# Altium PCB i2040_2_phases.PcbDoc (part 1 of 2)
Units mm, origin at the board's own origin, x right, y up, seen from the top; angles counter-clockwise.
Board outline 90 x 90 mm, 2 copper layers (Top Layer, Bottom Layer), stack 1.575 mm thick; 116 components, 66 nets, 276 pads, 142 vias.
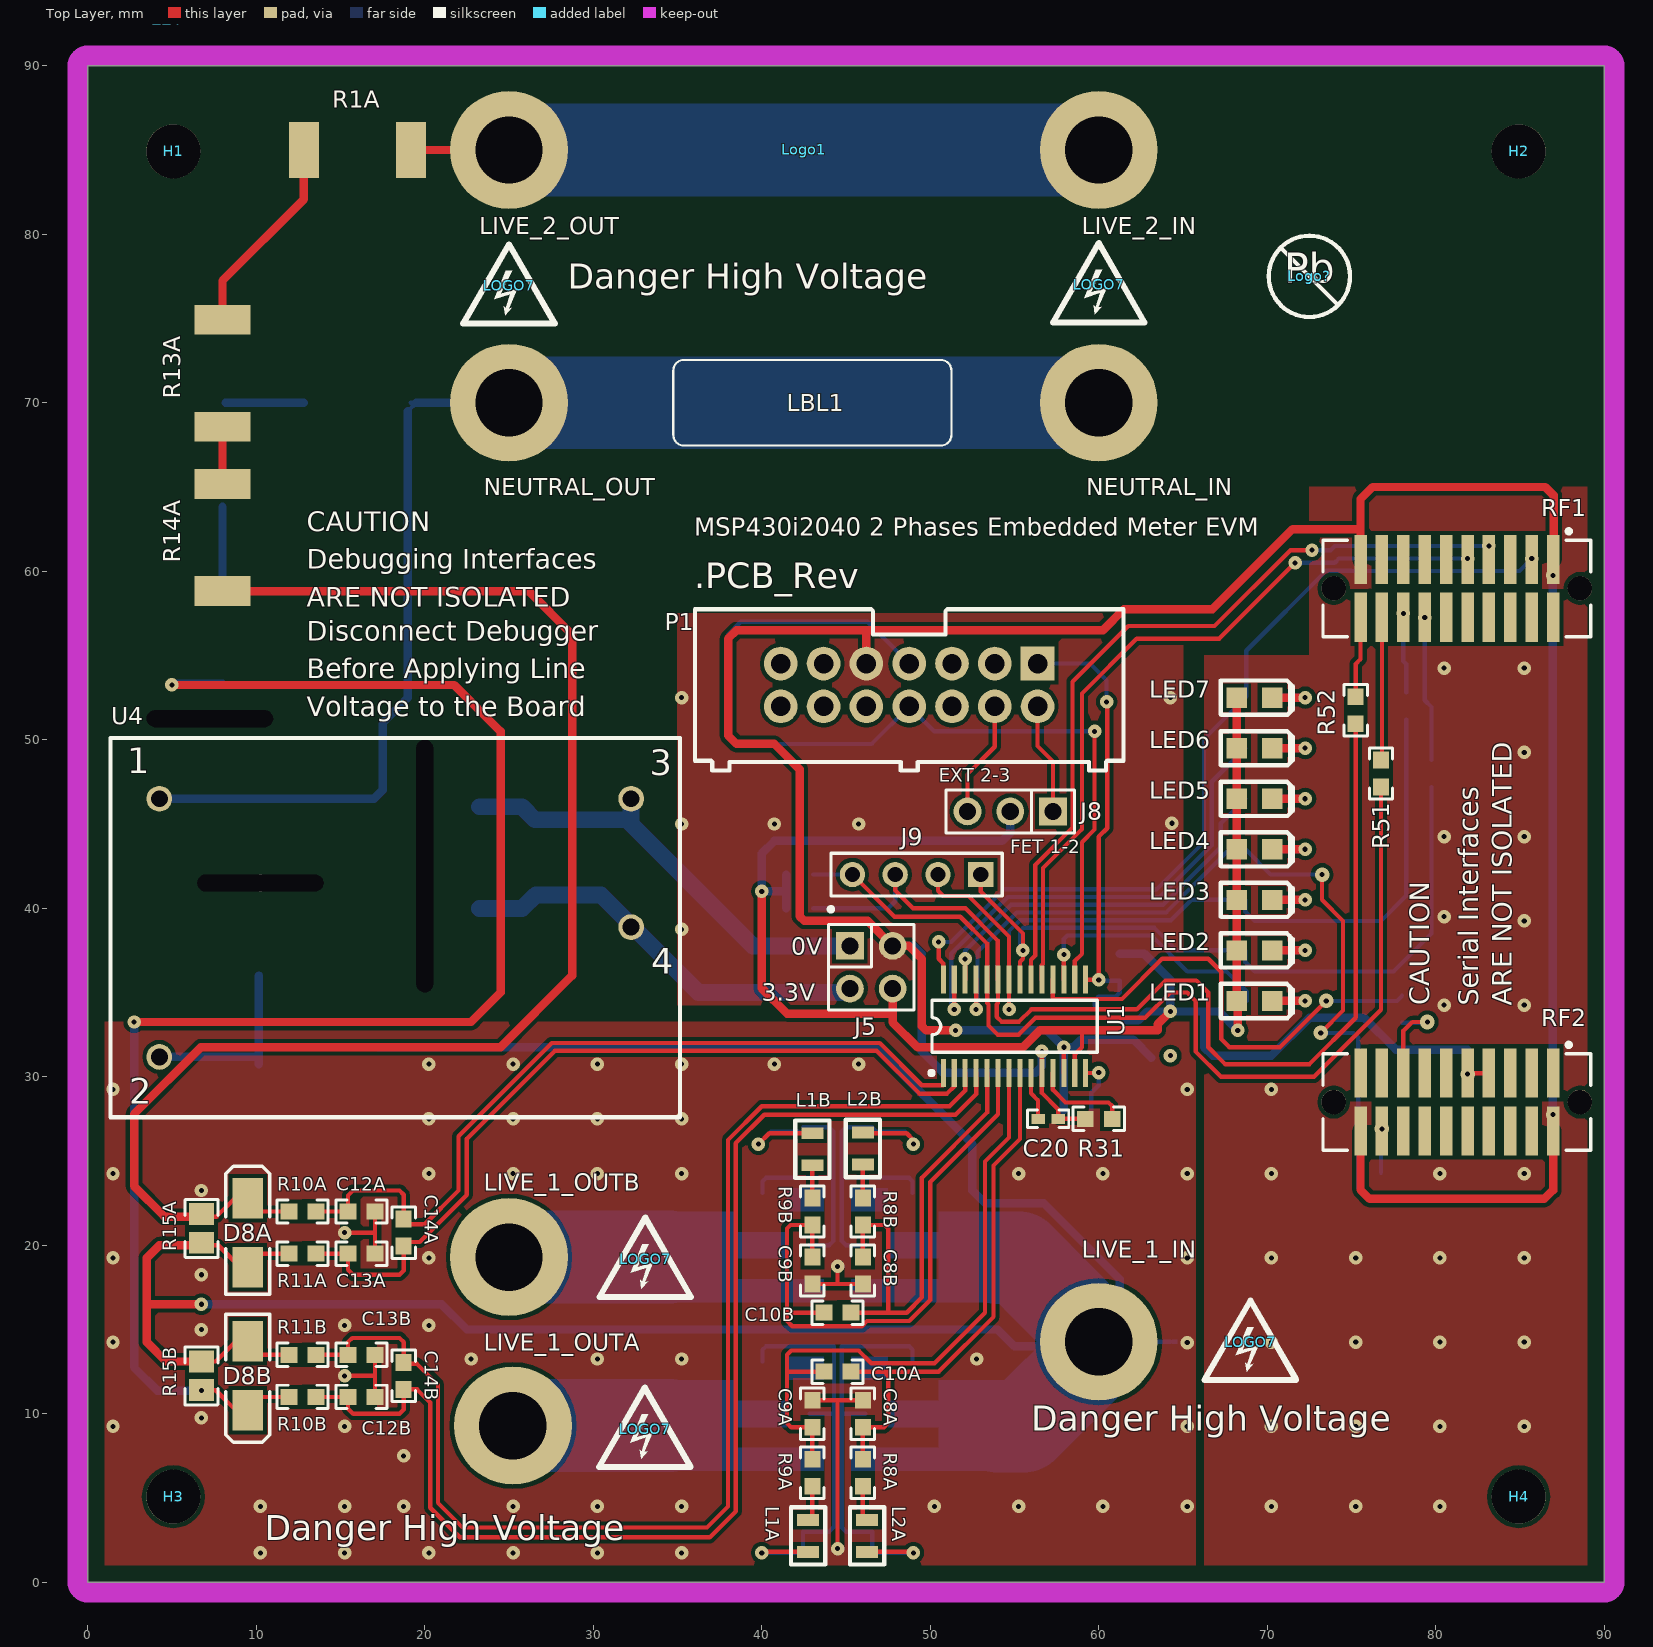
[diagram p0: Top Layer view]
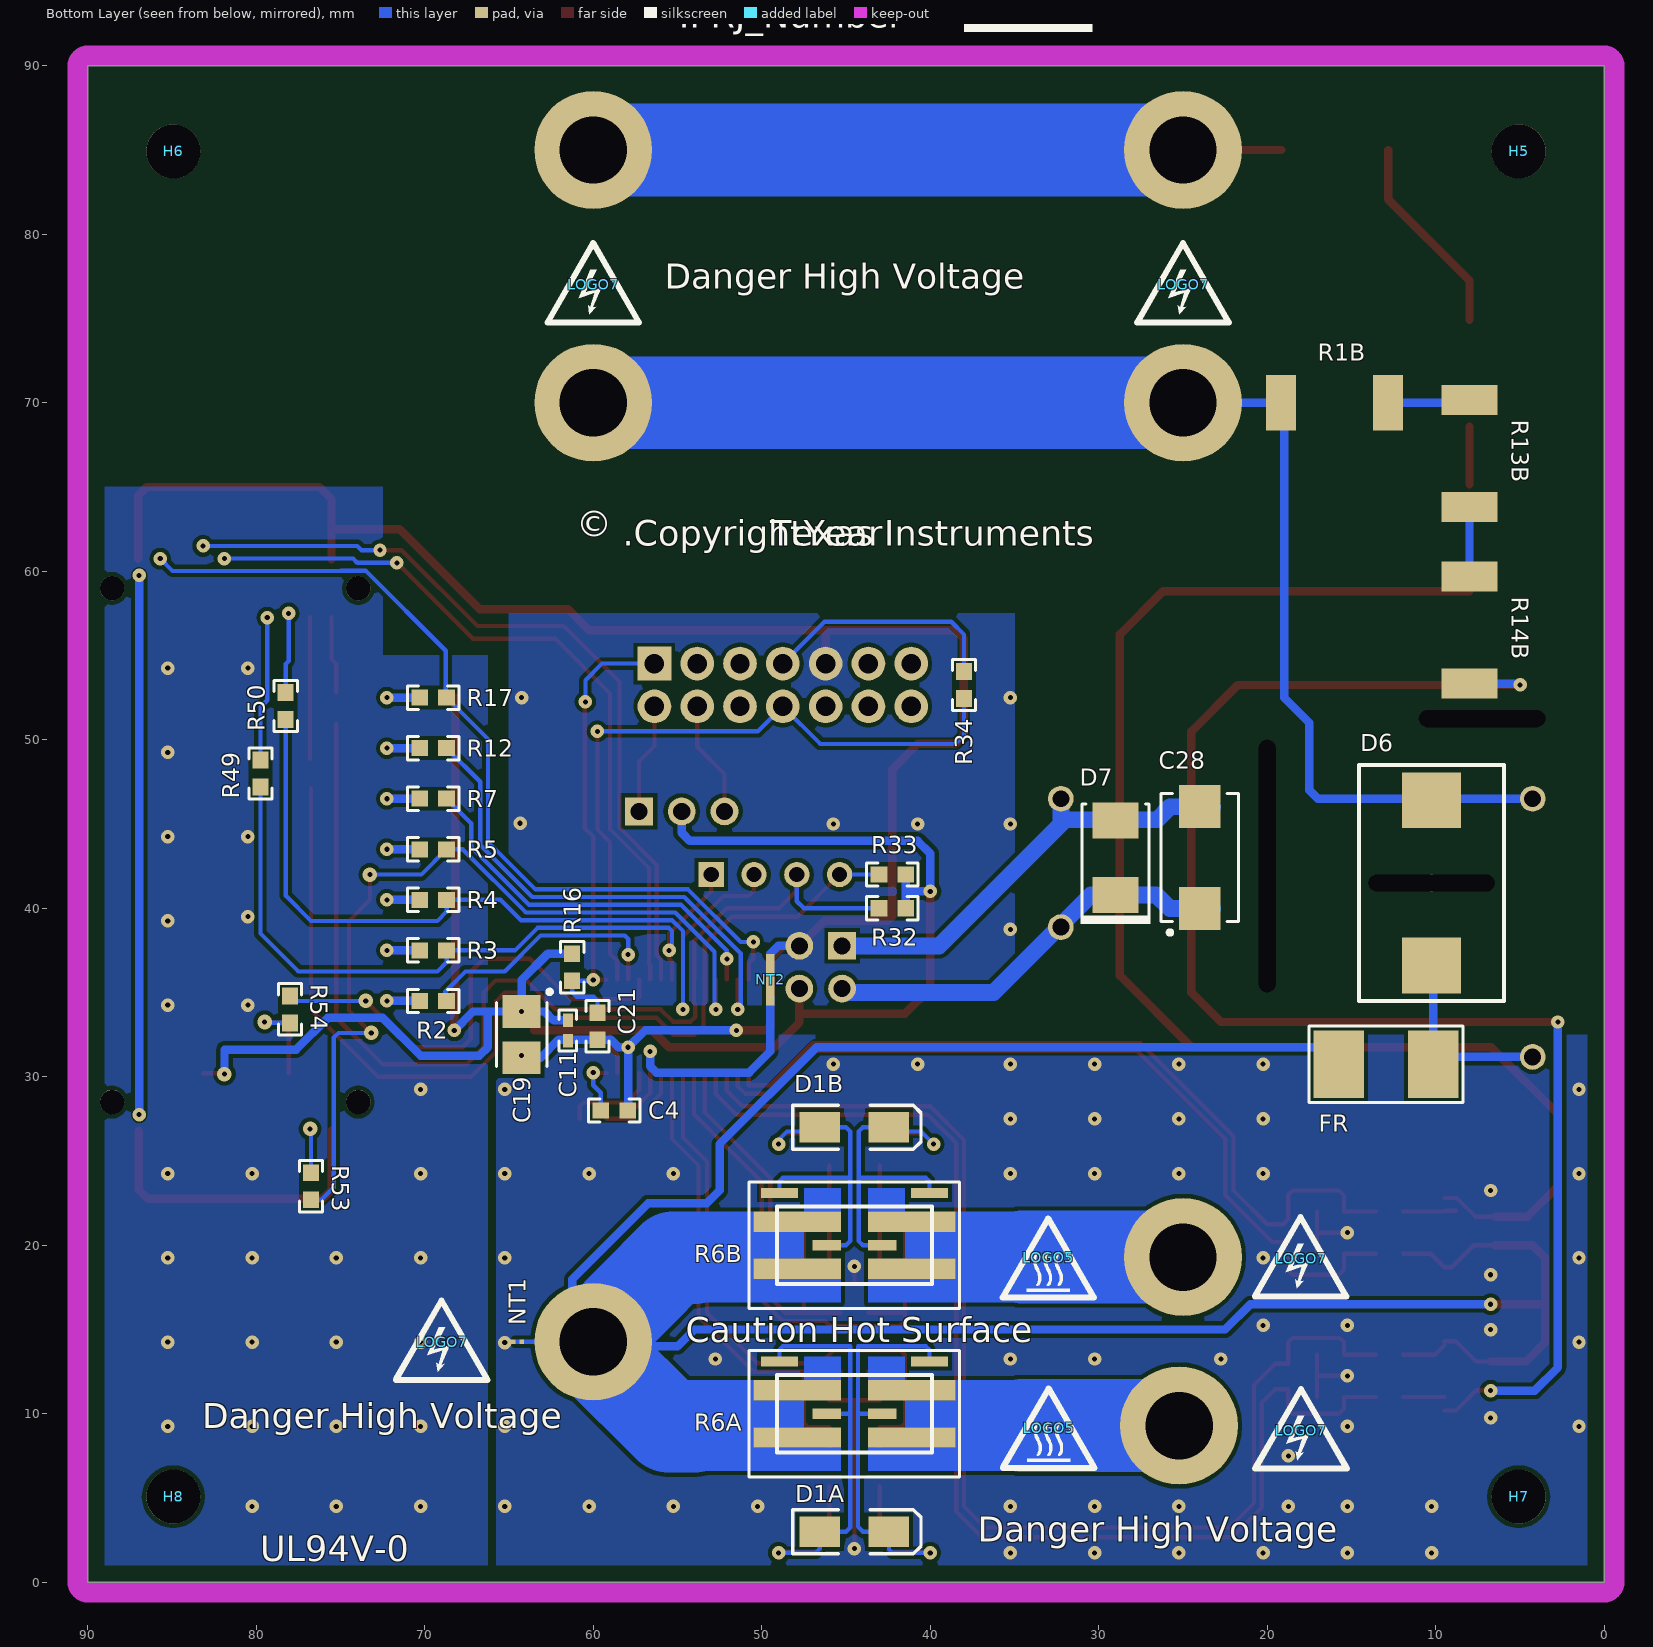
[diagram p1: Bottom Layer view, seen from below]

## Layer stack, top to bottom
Top Layer: signal copper 0.0356
Dielectric: core 1.5037, FR-4, Dk 4.8
Bottom Layer: signal copper 0.0356

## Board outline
0,0 90,0 90,90 0,90

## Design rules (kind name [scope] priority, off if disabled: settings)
AcuteAngle [All] p1: minimum=4.50000000000000E+0001 checktracksonly=FALSE
AssemblyTestPointUsage [All] p1: valid=2
Clearance Clearance_HV [InNet('LIVE2') vs OnLayer('Bottom Layer')] p1: gap=8
Clearance Clearance_BoardEdge_MountingHoles [OnCopper and InComponentClass('Mounting Holes') vs IsKeepOut] p2: gap=1.016
Clearance Clearance_BoardEdge_Poly [OnCopper and InPoly vs IsKeepOut] p3: gap=0.635
Clearance Clearance_BoardEdge [All vs IsKeepOut] p4: gap=1
Clearance Clearance_Poly [InPolygon] p5: gap=0.25
Clearance [All] p6: gap=0.203
ComponentClearance ComponentClearance_Shunt [InComponentClass('Header') vs InComponentClass('Shunt')] p1: gap=0 collisioncheckmode=3 verticalgap=0 showdistances=FALSE
ComponentClearance ComponentClearance_Logo [InComponentClass('Logo')] p2: gap=1.27 collisioncheckmode=3 verticalgap=0.254 showdistances=FALSE
ComponentClearance ComponentClearance_ScrewToNut [(HasFootprint('NY PMS 440 0025 PH')) vs (HasFootprint('Keystone_1902C'))] p3: gap=0.127 collisioncheckmode=3 verticalgap=0.254 showdistances=FALSE
ComponentClearance ComponentClearance_MountingHoles [InComponentClass('Mounting Holes')] p4: gap=5 collisioncheckmode=3 verticalgap=0 showdistances=FALSE
ComponentClearance ComponentClearance_SmallPassives [HasFootprint('0201*') or HasFootprint('0402*') or HasFootprint('0508') or HasFootprint('0603*') or HasFootprint('0612') or HasFootprint('0805*') or HasFootprint('0815*') or HasFootprint('0830*') or HasFootprint('1206*') or HasFootprint('1210*') or HasFootprint('1808*') or HasFootprint('1812*') or HasFootprint('1825*') or HasFootprint('2010*') or HasFootprint('2220*') or HasFootprint('2225*') or HasFootprint('2512*') or HasFootprint('2728*') or HasFootprint('3518*') vs HasFootprint('0201*') or HasFootprint('0402*') or HasFootprint('0508') or HasFootprint('0603*') or HasFootprint('0612') or HasFootprint('0805*') or HasFootprint('0815*') or HasFootprint('0830*') or HasFootprint('1206*') or HasFootprint('1210*') or HasFootprint('1808*') or HasFootprint('1812*') or HasFootprint('1825*') or HasFootprint('2010*') or HasFootprint('2220*') or HasFootprint('2225*') or HasFootprint('2512*') or HasFootprint('2728*') or HasFootprint('3518*')] p5: gap=0.5 collisioncheckmode=3 verticalgap=0.254 showdistances=FALSE
ComponentClearance ComponentClearance_THtoSMT [IsThruComponent vs IsSMTComponent] p6: gap=0.5 collisioncheckmode=3 verticalgap=0.762 showdistances=FALSE
ComponentClearance ComponentClearance_THtoTH [IsThruComponent vs IsThruComponent] p7: gap=1 collisioncheckmode=3 verticalgap=0.762 showdistances=FALSE
ComponentClearance [All] p8: gap=0.5 collisioncheckmode=3 verticalgap=0.254 showdistances=FALSE
DiffPairsRouting [All] p1: maxlimit=2.54 minlimit=0.254 mostfreqgap=0.254 maxuncoupledlength=25.4
FabricationTestPointUsage TestPointUsage [All] p1: valid=2 allowmultiple=FALSE
FabricationTestpoint Testpoint [All] p1: side=3 testpointundercomponent=TRUE minsize=1.016 maxsize=2.54 preferedsize=1.524 minholesize=0 maxholesize=1.016 preferedholesize=0.813 testpointgrid=0.025 allowsidetop=TRUE allowsidebottom=TRUE usegrid=TRUE gridtolerance=0
FanoutControl Fanout_LCC [IsLCC] p1: bgadir=Out bgaviamode=Centered fanoutstyle=Auto fanoutdirection=Alternating viagrid=0.025 // Fanout_LCC (Default Rule)
FanoutControl Fanout_BGA [IsBGA] p2: bgadir=Out bgaviamode=Centered fanoutstyle=Auto fanoutdirection=Alternating viagrid=0.025 // Fanout_BGA (Default Rule)
FanoutControl Fanout_Default [All] p4: bgadir=Out bgaviamode=Centered fanoutstyle=Auto fanoutdirection=Alternating viagrid=0.025 // Fanout_Default (Default Rule)
FanoutControl Fanout_Small [(CompPinCount < 5)] p5: bgadir=Out bgaviamode=Centered fanoutstyle=Auto fanoutdirection=OutThenIn viagrid=0.025 // Fanout_Small (Default Rule)
HoleSize [All] p1: absolutevalues=TRUE maxlimit=6.375 minlimit=0.203 maxpercent=80.000 minpercent=20.000
MinimumAnnularRing MinimumAnnularRing_ThermalPadVias [IsVia and InAnyComponent] p1: minimumring=0.15
MinimumAnnularRing [All] p2: minimumring=0.229
MinimumSolderMaskSliver MinimumSolderMaskSliver_Logo [InComponentClass('Logo') vs InComponentClass('Logo')] p1: minsoldermaskwidth=0.018
MinimumSolderMaskSliver [All] p2: minsoldermaskwidth=0.1
PlaneConnect [All] p1: planeconnectstyle=Relief reliefexpansion=0.254 reliefentries=4 reliefconductorwidth=0.254 reliefairgap=0.254
PolygonConnect [All] p1: connectstyle=Direct reliefconductorwidth=0.254 reliefentries=4 polygonreliefangle="90 Angle" airgapwidth=0.254
RoutingVias ThermalPadVias [IsVia and InAnyComponent] p1: holewidth=0.2 width=0.5 viastyle="Through Hole" minholewidth=0.2 minwidth=0.5 maxholewidth=0.33 maxwidth=0.6
RoutingVias [All] p2: holewidth=0.406 width=0.864 viastyle="Through Hole" minholewidth=0.2 minwidth=0.66 maxholewidth=1.016 maxwidth=1.651
SMDToCorner [All] p1: distance=30000
SilkToSilkClearance [All] p1: silktosilkclearance=0.127
SilkscreenOverComponentPads [All] p1: minsilkscreentomaskgap=0.127
SolderMaskExpansion [All] p1: expansion=0.05
Width Width_HV [InNetClass('HighVoltage')] p1: maxlimit=7 minlimit=0.254 preferedwidth=0.254
Width [All] p2: maxlimit=2.54 minlimit=0.152 preferedwidth=0.254 checkconnectedcopper=TRUE
14 further rules are at their usual default settings.

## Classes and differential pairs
component class Label: LBL1
component class AssemblyNote: ZZ1 ZZ2 ZZ3 ZZ4
component class Hardware_ANSI-B: H1 H2 H3 H4 H5 H6 H7 H8 LBL1 Logo1 ZZ1 ZZ2 ZZ3 ZZ4
component class Logo: Logo1
component class "Mounting Holes": H1 H2 H3 H4
component class Header: J5 J8
component class i2040-2-phases: 0.5 0.8 C4 C8A C8B C9A C9B C10A C10B C11 C12A C12B C13A C13B C14A C14B C19 C20 C21 C28 D1A D1B D6 D7 D8A D8B FR J5 J8 J9 L1A L1B L2A L2B LED1 LED2 LED3 LED4 LED5 LED6 LED7 LIVE_1_IN LIVE_1_OUTA LIVE_1_OUTB LIVE_2_IN LIVE_2_OUT LOGO5 LOGO7 Logo? NEUTRAL_IN NEUTRAL_OUT NT1 NT2 P1 R1A R1B R2 R3 R4 R5 R6A R6B R7 R8A R8B R9A R9B R10A R10B R11A R11B R12 R13A R13B R14A R14B R15A R15B R16 R17 R31 R32 R33 R34 R49 R50 R51 R52 R53 R54 RF1 RF2 U1 U4

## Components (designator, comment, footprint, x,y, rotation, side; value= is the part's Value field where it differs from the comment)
C4 "470nF" 0603 58.75,28 r180 bottom
C8A "06035A470JAT2A" 0603 46,10 r270 top
C8B "06035A470JAT2A" 0603 46,18.5 r90 top
C9A "06035A470JAT2A" 0603 43,10 r90 top
C9B "06035A470JAT2A" 0603 43,18.5 r270 top
C10A "GRM188R71C153KA01D" 0603 44.5,12.5 r0 top
C10B "GRM188R71C153KA01D" 0603 44.5,16 r0 top
C11 "0.1uF" 0402 61.5,32.75 r270 bottom
C12A "06035A470JAT2A" 0603 16.25,22 r0 top
C12B "06035A470JAT2A" 0603 16.25,11 r0 top
C13A "06035A470JAT2A" 0603 16.25,19.5 r180 top
C13B "06035A470JAT2A" 0603 16.25,13.5 r180 top
C14A "GRM188R71C153KA01D" 0603 18.75,20.75 r270 top
C14B "GRM188R71C153KA01D" 0603 18.75,12.25 r90 top
C19 "293D106X0010B2TE3" 3528-21 64.25,32.5 r270 bottom
C20 "0.1uF" 0402 57,27.5 r0 top
C21 "C0603X222K5RACTU" 0603 59.75,33 r270 bottom
C28 "293D227X96R3D2TE3" 7343-31 24,43 r90 bottom
D1A "SMAJ5.0CA" DSO-C2/X1.8 44.5,3 r180 bottom
D1B "SMAJ5.0CA" DSO-C2/X1.8 44.5,27 r180 bottom
D6 "V320SM7" V320SM7 10.25,41.5 r90 bottom
D7 "SMBJ7.0A-13-F" SMB 29,43 r90 bottom
D8A "SMAJ5.0CA" DSO-C2/X1.8 9.5,20.75 r90 top
D8B "SMAJ5.0CA" DSO-C2/X1.8 9.5,12.25 r270 top
FR "6125FA1A" 6125FA 12.95,30.75 r0 bottom
H1 "NY PMS 440 0025 PH" "NY PMS 440 0025 PH" 5.08,84.92 r0 top locked
H2 "NY PMS 440 0025 PH" "NY PMS 440 0025 PH" 84.92,84.92 r0 top locked
H3 "NY PMS 440 0025 PH" "NY PMS 440 0025 PH" 5.08,5.08 r0 top locked
H4 "NY PMS 440 0025 PH" "NY PMS 440 0025 PH" 84.92,5.08 r0 top locked
H5 "1902C" Keystone_1902C 5.08,84.92 r180 bottom locked
H6 "1902C" Keystone_1902C 84.92,84.92 r180 bottom locked
H7 "1902C" Keystone_1902C 5.08,5.08 r180 bottom locked
H8 "1902C" Keystone_1902C 84.92,5.08 r180 bottom locked
J5 "TSW-102-07-G-D" TSW-102-07-G-D 46.5,36.5 r270 top
J8 "PBC03SAAN" PBC03SAAN 54.75,45.75 r180 top
J9 "Header 4" HDR1X4 53,42 r180 top
L1A "BLM21BD121SN1D" YW0805 42.75,2.75 r270 top
L1B "BLM21BD121SN1D" YW0805 43,25.7 r90 top
L2A "BLM21BD121SN1D" YW0805 46.25,2.75 r270 top
L2B "BLM21BD121SN1D" YW0805 46,25.75 r90 top
LBL1 "Size: 0.65\" x 0.20 \"" Label_650x200 43,70 r0 top
LED1 "Used in BOM report" 0805-LED 69.25,34.5 r0 top
LED2 "Used in BOM report" 0805-LED 69.25,37.5 r0 top
LED3 "Used in BOM report" 0805-LED 69.25,40.5 r0 top
LED4 "Used in BOM report" 0805-LED 69.25,43.5 r0 top
LED5 "Used in BOM report" 0805-LED 69.25,46.5 r0 top
LED6 "Used in BOM report" 0805-LED 69.25,49.5 r0 top
LED7 "Used in BOM report" 0805-LED 69.25,52.5 r0 top
LIVE_1_IN "LIVE_1" "Hole for Banana Socket"#1 52.75,8.725 r0 top
LIVE_1_OUTA "LIVE_1A" "Hole for Banana Socket"#2 25.234,9.3 r90 top
LIVE_1_OUTB "LIVE_1B" "Hole for Banana Socket"#3 84.5,9 r0 top
LIVE_2_IN "LIVE_2" "Hole for Banana Socket"#4 55,80 r0 top
LIVE_2_OUT "LIVE_2A" "Hole for Banana Socket"#5 35,80 r0 top
Logo1 "Texas Instruments" TI_Stacked_SolderMask_Small 42.5,85 r0 top
LOGO5 "CAUTION HOT SURFACE" IEC_HotSurface_Small 33,19.25 r180 bottom
LOGO5 "CAUTION HOT SURFACE" IEC_HotSurface_Small 32.975,9.154 r180 bottom
LOGO7 "DANGER HIGH VOLTAGE" IEC_HighVoltage_Small 69,14.25 r180 bottom
LOGO7 "DANGER HIGH VOLTAGE" IEC_HighVoltage_Small 18.025,19.2 r180 bottom
LOGO7 "DANGER HIGH VOLTAGE" IEC_HighVoltage_Small 18,9 r180 bottom
LOGO7 "DANGER HIGH VOLTAGE" IEC_HighVoltage_Small 60,77 r180 bottom
LOGO7 "DANGER HIGH VOLTAGE" IEC_HighVoltage_Small 33.089,19.161 r0 top
LOGO7 "DANGER HIGH VOLTAGE" IEC_HighVoltage_Small 60,77 r0 top
LOGO7 "DANGER HIGH VOLTAGE" IEC_HighVoltage_Small 69,14.25 r0 top
LOGO7 "DANGER HIGH VOLTAGE" IEC_HighVoltage_Small 33.064,9.078 r0 top
LOGO7 "DANGER HIGH VOLTAGE" IEC_HighVoltage_Small 25,77 r180 bottom
LOGO7 "DANGER HIGH VOLTAGE" IEC_HighVoltage_Small 25,76.933 r0 top
Logo? "Pb-Free Symbol" Pb-Free_Overlay_Medium 72.5,77.5 r0 top
NEUTRAL_IN "NEUTRAL" "Hole for Banana Socket"#6 55,60 r0 top
NEUTRAL_OUT "NEUTRAL" "Hole for Banana Socket"#7 35,60 r0 top
NT1 "Net-Tie" Net-Tie_10mil 64.5,14.275 r180 bottom net-tie (schematic designator NT11)
NT2 "Net-Tie" Net-Tie_20milWide_60milLong 49.5,35.75 r90 bottom net-tie
P1 "MHDR2X7" 2X7BOXHEADER 48.75,53.25 r180 top
R1A "330k" R2512 16,85 r180 top
R1B "330k" R2512 16,70 r180 bottom
R2 "390" 0603 69.5,34.5 r0 bottom
R3 "390" 0603 69.5,37.5 r0 bottom
R4 "390" 0603 69.5,40.5 r0 bottom
R5 "390" 0603 69.5,43.5 r0 bottom
R6A "WSL40262L000FEB" "Current Sensing Pad" 44.5,10 r0 bottom
R6B "WSL40262L000FEB" "Current Sensing Pad" 44.5,20 r0 bottom
R7 "390" 0603 69.5,46.5 r0 bottom
R8A "1.00k" 0603 46,6.5 r90 top
R8B "1.00k" 0603 46,22 r270 top
R9A "1.00k" 0603 43,6.5 r90 top
R9B "1.00k" 0603 43,22 r270 top
R10A "100" 0603 12.75,22 r0 top
R10B "100" 0603 12.75,11 r0 top
R11A "1.00k" 0603 12.75,19.5 r0 top
R11B "1.00k" 0603 12.75,13.5 r0 top
R12 "390" 0603 69.5,49.5 r0 bottom
R13A "330k" R2512 8,71.75 r270 top
R13B "330k" R2512 8,67 r270 bottom
R14A "330k" R2512 8,62 r270 top
R14B "330k" R2512 8,56.5 r270 bottom
R15A "1.50k" 0805 6.75,21 r90 top
R15B "1.50k" 0805 6.75,12.25 r270 top
R16 "4.7k" 0603 61.25,36.5 r270 bottom
R17 "390" 0603 69.5,52.5 r0 bottom
R31 "Open" 0603 60,27.5 r0 top
R32 "Open" 0603 42.25,40 r180 bottom
R33 "Open" 0603 42.25,42 r180 bottom
R34 "330" 0603 38,53.25 r90 bottom
R49 "0" 0603 79.75,48 r270 bottom
R50 "0" 0603 78.25,52 r270 bottom
R51 "0" 0603 76.75,48 r270 top
R52 "0" 0603 75.25,51.75 r270 top
R53 "0" 0603 76.75,23.5 r270 bottom
R54 "0" 0603 78,34 r270 bottom
RF1 "TFM-110-02-S-D-A-K-TR" Samtec_TFM-110-02-S-D-A-K 81.25,58.98 r180 top
RF2 "TFM-110-02-S-D-A-K-TR" Samtec_TFM-110-02-S-D-A-K 81.25,28.5 r180 top
U1 "MSP430i2040PW" TSSO10x6-G28 55,33 r0 top
U4 "VSK-S1-3R3U" VSK-S1 4.25,46.5 r0 top
ZZ1 "This Assembly Note is for PCB labels only" AssemblyNoteLabel 4.699,100.025 r0 top
ZZ2 "These assemblies are ESD sensitive, ESD precautions shall be observed." AssemblyNote 4.699,97.259 r0 top
ZZ3 "These assemblies must be clean and free from flux and all contaminants. Use of no clean flux is not acceptable." AssemblyNote 4.699,95.01 r0 top
ZZ4 "These assemblies must comply with workmanship standards IPC-A-610 Class 2, unless otherwise specified." AssemblyNote 4.699,92.761 r0 top

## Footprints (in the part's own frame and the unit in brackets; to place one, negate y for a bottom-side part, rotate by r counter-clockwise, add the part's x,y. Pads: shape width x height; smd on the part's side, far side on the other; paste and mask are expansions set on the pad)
2X7BOXHEADER [mm]
  rect 2x2 hole 1.15: 1(-7.62,-1.27)
  round 2 hole 1.15: 2(-7.62,1.27) 3(-5.08,-1.27) 4(-5.08,1.27) 5(-2.54,-1.27) 6(-2.54,1.27) 7(0,-1.27) 8(0,1.27) 9(2.54,-1.27) 10(2.54,1.27) 11(5.08,-1.27) 12(5.08,1.27) 13(7.62,-1.27) 14(7.62,1.27)
  silkscreen extent -12.72,-4.5 12.72,5.08
0402 [mm] "0402 from SM-752 data"
  rect 0.8x0.6 smd: 1(-0.6,0) 2(0.6,0)
  silkscreen extent -1.22,-0.52 1.22,0.52, body extent -0.55,-0.3 0.55,0.3, height 0.6
0603 [mm] "0603 from SM-752 data"
  rect 1x0.95 smd: 1(-0.8,0) 2(0.8,0)
  silkscreen extent -1.52,-0.69 1.52,0.69, body extent -0.87,-0.47 0.87,0.47, height 0.85
0805 [mm] "0805 from SM-752 data"
  rect 1.3x1.5 smd: 1(-0.85,0) 2(0.85,0)
  silkscreen extent -1.72,-0.97 1.72,0.97, body extent -1.1,-0.72 1.1,0.72, height 1.1
0805-LED [mm]
  rect 1.2x1.2 smd: 1(-1.055,-0.005) 2(1.045,-0.005)
  silkscreen extent -2.01,-1.02 2.26,1.01
3528-21 [mm] "Medium Density IPC, based on SM-782 section 8.4"
  rect 1.95x2.25 smd: 1(-1.375,0) 2(1.375,0)
  silkscreen extent -2.66,-1.5 1.9,1.79, body extent -1.85,-1.5 1.85,1.5, height 2.1
6125FA [mm] "Cooper Bussman 6125FA Brick Fuses, recommended land pattern OC-2531 Rev. I 3/07"
  rect 3x4 smd: 1(-2.8,0) 2(2.8,0)
  silkscreen extent -4.57,-2.27 4.58,2.28, body extent -3.17,-1.42 3.17,1.41, height 2.84
7343-31 [mm] "Medium Density based on Kemet T495 dimensions"
  rect 2.55x2.45 smd: 1(-3.025,0) 2(3.025,0)
  silkscreen extent -4.56,-2.3 3.8,2.3, body extent -3.8,-2.3 3.8,2.3, height 3.1
AssemblyNote [mm] "Assembly Note"
AssemblyNoteLabel [mm] "Assembly Note for PCB Labels"
"Current Sensing Pad" [mm] "Current Sensing Pad for 2512"
  rect 5.2x1.2 smd: 1(3.4,-1.4) 1(3.4,1.4) 2(-3.4,-1.4) 2(-3.4,1.4)
  rect 1.7x0.6 smd: 3(1.65,0) 4(-1.65,0)
  rect 2.2x0.6 smd: 5(4.45,-3.1) 6(-4.45,-3.1)
  Top Layer region: 0.8,3.4 6,3.4 6,2 0.8,2
  Top Layer region: -6,3.4 -0.8,3.4 -0.8,2 -6,2
  Top Layer region: -6,0.8 -3,0.8 -3,-0.8 -6,-0.8
  Top Layer region: 3,0.8 6,0.8 6,-0.8 3,-0.8
  Top Layer region: -3,-2 -0.8,-2 -0.8,-3.4 -3,-3.4
  Top Layer region: 0.8,-2 3,-2 3,-3.4 0.8,-3.4
  silkscreen extent -6.25,-3.75 6.25,3.75
DSO-C2/X1.8 [mm] "DO-214-AC/SMA; 2 C-Bend Leads; Body 5 x 2.7 mm, inc. leads (LxW)"
  rect 2.4x1.8 smd: 1(-2.05,0) 2(2.05,0)
  silkscreen extent -3.65,-1.3 3.95,1.3
HDR1X4 [mm] "Connector; Header; 4 Position"
  rect 1.5x1.5 hole 0.9: 1(0,0)
  round 1.5 hole 0.9: 2(2.54,0) 3(5.08,0) 4(7.62,0)
  silkscreen extent -1.27,-1.27 8.89,1.27
"Hole for Banana Socket"#1 [mm] "Hole for Banana Socket"
  round 7 hole 4: 1(7.25,5.55)
"Hole for Banana Socket"#2 [mm] "Hole for Banana Socket"
  round 7 hole 4: 1(0,0)
"Hole for Banana Socket"#3 [mm] "Hole for Banana Socket"
  round 7 hole 4: 1(-59.5,10.3)
"Hole for Banana Socket"#4 [mm] "Hole for Banana Socket"
  round 7 hole 4: 1(5,5)
"Hole for Banana Socket"#5 [mm] "Hole for Banana Socket"
  round 7 hole 4: 1(-10,5)
"Hole for Banana Socket"#6 [mm] "Hole for Banana Socket"
  round 7 hole 4: 1(5,10)
"Hole for Banana Socket"#7 [mm] "Hole for Banana Socket"
  round 7 hole 4: 1(-10,10)
IEC_HighVoltage_Small [mm]
  silkscreen extent -2.72,-2.24 2.72,2.47
IEC_HotSurface_Small [mm]
  silkscreen extent -2.72,-2.36 2.72,2.35
Keystone_1902C [mm] "Hex Standoff, 4-40 threaded, nylon"
  body extent -3.68,-3.2 3.71,3.2, height 12.73
Label_650x200 [mm] "Thermal Transfer Label"
  silkscreen extent -8.25,-2.54 8.26,2.54, body extent -8.27,-2.55 8.27,2.55, height 0.03
Net-Tie_10mil [mil] "10mil net tie, no solder mask opening, no solder paste"
  rect 10x10 smd paste-5 mask-5: 1(-10,0) 2(10,0)
  Top Layer region: -6,5 6,5 6,-5 -6,-5
Net-Tie_20milWide_60milLong [mil] "20mil net tie, no solder mask opening, no solder paste"
  rect 60x20 smd paste-10 mask-10: 1(-30,0) 2(30,0)
"NY PMS 440 0025 PH" [mm] "4-40 nylon screw and mounting hole"
  round 3.2 hole 3.2: 1(0,0)
  body extent -3.3,-3.3 3.3,3.3, height 2.69
Pb-Free_Overlay_Medium [mm]
  silkscreen extent -2.41,-2.41 2.41,2.41
PBC03SAAN [mm] "Sullins 100mil, 1x3, 230 mil above insulator"
  rect 1.65x1.65 hole 1.016: 1(-2.54,0)
  round 1.65 hole 1.016: 2(0,0) 3(2.54,0)
  silkscreen extent -3.81,-1.27 3.81,1.27, body extent -3.81,-1.27 3.81,1.27, height 8.38
R2512 [mil]
  rect 70x130 smd: 1(-125,0) 2(125,0)
Samtec_TFM-110-02-S-D-A-K [mm] "Samtec"
  rect 0.74x2.92 smd paste+0: 1(-5.715,-1.715) 2(-5.715,1.715) 3(-4.445,-1.715) 4(-4.445,1.715) 5(-3.175,-1.715) 6(-3.175,1.715) 7(-1.905,-1.715) 8(-1.905,1.715) 9(-0.635,-1.715) 10(-0.635,1.715) 11(0.635,-1.715) 12(0.635,1.715) 13(1.905,-1.715) 14(1.905,1.715) 15(3.175,-1.715) 16(3.175,1.715) 17(4.445,-1.715) 18(4.445,1.715) 19(5.715,-1.715) 20(5.715,1.715)
  round 1.45 hole 1.45 unplated paste+0: ""(-7.305,0) ""(7.305,0)
  silkscreen extent -7.94,-3.51 7.94,2.86, body extent -7.95,-2.98 7.93,2.99, height 5.85
SMB [mm] "Molded Diode, 2-Leads, Body 5.4x3.6mm, IPC Medium Density, based on OnSemi component dimensions"
  rect 2.159x2.743 smd: 1(-2.21,0) 2(2.21,0)
  silkscreen extent -3.94,-2.08 3.17,2.08, body extent -2.7,-1.8 2.7,1.8, height 2.32
TI_Stacked_SolderMask_Small [mm]
  rect 0x0 smd paste-3.175 mask-3.175: 0(0,0)
TSSO10x6-G28 [mm] "Shrink Small Outline; 28 Leads; Body Width 4.4 mm; Pitch 0.65 mm"
  rect 0.3x1.65 smd: 1(-4.225,-2.775) 2(-3.575,-2.775) 3(-2.925,-2.775) 4(-2.275,-2.775) 5(-1.625,-2.775) 6(-0.975,-2.775) 7(-0.325,-2.775) 8(0.325,-2.775) 9(0.975,-2.775) 10(1.625,-2.775) 11(2.275,-2.775) 12(2.925,-2.775) 13(3.575,-2.775) 14(4.225,-2.775) 15(4.225,2.775) 16(3.575,2.775) 17(2.925,2.775) 18(2.275,2.775) 19(1.625,2.775) 20(0.975,2.775) 21(0.325,2.775) 22(-0.325,2.775) 23(-0.975,2.775) 24(-1.625,2.775) 25(-2.275,2.775) 26(-2.925,2.775) 27(-3.575,2.775) 28(-4.225,2.775)
  silkscreen extent -5.05,-2.9 4.9,1.55
TSW-102-07-G-D [mm] "Samtec 100mil, 2x2, 230 mil above insulator"
  rect 1.65x1.65 hole 1.016 mask+0: 1(-1.27,-1.27)
  round 1.65 hole 1.016 mask+0: 2(-1.27,1.27) 3(1.27,-1.27) 4(1.27,1.27)
  silkscreen extent -3.56,-2.54 2.54,2.54, body extent -2.54,-2.54 2.54,2.54, height 8.38
V320SM7 [mm] "SMD MOV"
  rect 3.3x3.5 smd: 1(-4.9,0) 2(4.9,0)
  silkscreen extent -7,-4.3 7,4.3, body extent -6,-4.1 6,4, height 6
VSK-S1 [mil] "On board block power supply"
  round 60 hole 39.37: 1(0,0) 2(0,-603.31) 3(1102.36,0) 4(1102.36,-300)
  silkscreen extent -114,-744 1217,142, body extent -98,-720 1193,118, height 709
YW0805 [mm]
  rect 0.7x1.3 smd: 1(0.946,0) 2(-0.954,0)
  silkscreen extent -1.71,-1.02 1.7,1.02

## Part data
C4: library part Capacitor, "CAP, CERM, 470nF, 16V, [TempCo], xx%, [PackageReference]"
C8A C8B C9A C9B C12A C12B C13A C13B: "CAP, CERM, 47pF, 50V, +/-5%, C0G/NP0, 0603"
C10A C10B C14A C14B: "CAP, CERM, 0.015uF, 16V, +/-10%, X7R, 0603"
C11 C20: library part C1005X5R1A104K, "CAP, CERM, 0.1uF, 10V, +/-10%, X5R, 0402"
C19: "CAP, TANT, 10uF, 10V, +/-20%, 2.5 ohm, 3528-21 SMD"
C21: "CAP, CERM, 2200pF, 50V, +/-10%, X7R, 0603"
C28: "CAP, TANT, 220uF, 6.3V, +/-10%, 0.6 ohm, 7343-31 SMD"
D7: "Diode, TVS, Uni, 7V, 600W, SMB"
FR: "Fuse, 1A,125V, SMD"
H1 H2 H3 H4: "Machine Screw, Round, #4-40 x 1/4, Nylon, Philips panhead"
H5 H6 H7 H8: "Standoff, Hex, 0.5\"L #4-40 Nylon"
J5: "Header, TH, 100mil, 2x2, Gold plated, 230 mil above insulator"
J8: "Header, TH, 100mil, 1x3, Gold plated, 230 mil above insulator"
J9: "Header, 4-Pin"
L1A L1B L2A L2B: library part Inductor, "Inductor, FERRITE CHIP 120 OHM 0805"
LBL1: library part THT-14-423-10, "Thermal Transfer Printable Labels, 0.650\" W x 0.200\" H - 10,000 per roll"
LED1 LED5: library part LED-0805, "Red"
LED2 LED6: library part LED-0805, "Green"
LED3 LED7: library part LED-0805, "Blue"
LED4: library part LED-0805, "White"
LIVE_1_IN LIVE_1_OUTA LIVE_1_OUTB LIVE_2_IN LIVE_2_OUT: library part "Hole for Banana Socket (Red)"
Logo1: library part TI_Logo, "Texas Instrument Corporate Signature"
LOGO5 LOGO5: library part IEC_HotSurface, "IEC 61010-1 Hot Surface Warning"
LOGO7 LOGO7 LOGO7 LOGO7 LOGO7 LOGO7 LOGO7 LOGO7 LOGO7 LOGO7: library part IEC_HighVoltage, "IEC 61010-1 High Voltage Warning"
Logo?: library part Pb-Free
NEUTRAL_IN NEUTRAL_OUT: library part "Hole for Banana Socket (Black)"
NT1 NT2: "Single point connection between nets."
P1: "Header, 7-Pin, Dual row"
R1A R1B R13A R13B R14A R14B: library part R2512, "Resistor, 330kOhm, 1W, 1%"
R2 R3 R4 R5 R7 R12 R17: library part RC0603JR-07390RL, "RES, 390 ohm, 5%, 0.1W, 0603"
R6A R6B: library part ULRB12512R0005FLFSLT, "Shunt Resistor"
R8A R8B R9A R9B R11A R11B: library part CRCW06031K00FKEA, "RES, 1.00k ohm, 1%, 0.1W, 0603"
R10A R10B: library part CRCW0603100RFKEA, "RES, 100 ohm, 1%, 0.1W, 0603"
R15A R15B: library part CRCW08051K50FKEA, "RES, 1.50k ohm, 1%, 0.125W, 0805"
R16: library part CRCW06034K70JNEA, "RES, 4.7k ohm, 5%, 0.1W, 0603"
R31: library part Resistor, "RES, Open ohm, x%, xW, 0603"
R32 R33: library part Resistor, "RES, xxx ohm, x%, xW, [PackageReference]"
R34: library part CRCW0603330RJNEA, "RES, 330 ohm, 5%, 0.1W, 0603"
R49 R50 R51 R52 R53 R54: library part CRCW06030000Z0EA, "RES, 0 ohm, 5%, 0.1W, 0603"
RF1 RF2: "CONN SHRD HDR HDR 20 POS 1.27MM SLDR ST SMD"
U1: library part MSP430i2040, "MSP430i2040"
U4: library part VSK-S1, "On board block power suppply"
ZZ1: library part AssemblyNoteLabel
ZZ2 ZZ3 ZZ4: library part AssemblyNote

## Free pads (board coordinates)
  round 1 hole 1 slot 7.5 at 0 deg: 0(7.25,51.25) 0(10.25,41.5)
  round 1 hole 1 slot 15 at 90 deg: 0(20,42.5)

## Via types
v1: diameter 0.8, hole 0.3, Top Layer to Bottom Layer, 134 vias
v2: diameter 0.864, hole 0.3, Top Layer to Bottom Layer, 6 vias
v3: diameter 0.8, hole 0.3, Top Layer to Bottom Layer, tented top, 2 vias

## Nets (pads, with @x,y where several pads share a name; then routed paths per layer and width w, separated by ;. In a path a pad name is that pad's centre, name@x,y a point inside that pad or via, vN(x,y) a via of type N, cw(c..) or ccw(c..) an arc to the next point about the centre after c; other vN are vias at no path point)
0V: C28.2 D7.2 J5.1 U4.3 | length 27
  Bottom Layer w1: C28.2@23.25,46.025 25.775,46.025 26.55,45.25 31.25,45.25 ; 31,45.25 31.25,45.25 ; U4.3@32.25,46.5 32.25,45.25 ; J5.1@45.23,37.77 39.48,37.77 32.25,45 32.25,45.25 ; 31.25,45.25 32.25,45.25
3.3V: C28.1 D7.1 J5.3 U4.4 | length 24.9
  Bottom Layer w1: C28.1@23.25,39.975 25.775,39.975 26.59,40.79 28.75,40.79 30.46,40.79 36.25,35 45.23,35 J5.3@45.23,35.23
AGND: C8A.1 C8B.1 C9A.2 C9B.2 C12A.2 C12B.2 C13A.1 C13B.1 C20.2 NT1.1 NT2.1 R31.1 U1.10 | length 42.4
  Top Layer w0.254: v1(15.25,12.25) 16.25,12.25 17.05,12.25 ; v1(15.25,20.75) 17.05,20.75 ; C12B.2@17.05,11 17.05,12.25 ; C13B.1@17.05,13.5 17.05,12.25 ; C13A.1@17.05,19.5 17.05,20.75 ; C12A.2@17.05,22 17.05,20.75 ; C9A.2@43,10.8 44.5,10.8 ; C9B.2@43,17.7 44.5,17.7 ; v1(44.5,2) 44.5,10.8 ; v1(44.5,18.75) 44.5,17.7 ; C8A.1@46,10.8 44.5,10.8 ; C8B.1@46,17.7 44.5,17.7 ; v1(56.625,31.5) U1.10@56.625,30.225 56.625,29.031 57.6,28.056 C20.2@57.6,27.5 R31.1@59.2,27.5
  Bottom Layer w0.5: NT2.1@49.5,34.75 49.5,31.5 50.75,30.25 56.25,30.25 56.625,30.625 v1(56.625,31.5)
  other v1: 10.25,1.75 15.25,1.75 20.25,1.75 25.25,1.75 30.25,1.75 35.25,1.75 10.25,4.5 15.25,4.5 18.75,4.5 25.25,4.5 30.25,4.5 35.25,4.5 50.25,4.5 60.25,4.5 65.25,4.5 18.75,7.5 1.5,9.25 15.25,9.25 65.25,9.25 6.75,9.75 22.75,13.25 30.25,13.25 35.25,13.25 52.75,13.25 65.25,14.225 1.5,14.25 6.75,15 15.25,15.25 20.25,15.25 6.75,18.25 1.5,19.25 20.25,19.25 65.25,19.25 6.75,23.25 1.5,24.25 20.25,24.25 25.25,24.25 30.25,24.25 35.25,24.25 55.25,24.25 65.25,24.25 20.25,27.5 25.25,27.5 30.25,27.5 35.25,27.5 1.5,29.25 65.25,29.25 20.25,30.75 25.25,30.75 30.25,30.75 35.25,30.75 40.75,30.75 45.75,30.75
  other v3: 55.25,4.5 60.25,24.25
DGND: C4.2 C11.2 C19.2 C21.2 J5.2 NT2.2 P1.9 RF1.1 RF1.19 RF2.2 RF2.20 U1.12 | length 166.4
  Top Layer w0.254: 46.21,56.46 46.25,56.5 ; U1.12@57.925,30.225 57.925,31.748 v1(57.927,31.75) ; RF2.20@75.5,26.75 RF2.20@75.535,26.785 ; 86.93,23.25 86.965,23.25 ; RF1.1@86.965,60.695 RF1.1@87,60.73
  Top Layer w0.5: P1.9@46.21,54.52 46.21,56.46 ; v1(51.5,32.75) 49.75,32.75 49.5,33 49.5,37 48.73,37.77 J5.2@47.77,37.77 46.29,39.25 42.526,39.25 42.25,39.526 42.25,48.25 40.75,49.75 38.5,49.75 38,50.25 38,56 38.5,56.5 46.25,56.5 60.25,56.5 61.5,57.75 66.75,57.75 71.5,62.5 75.535,62.5 ; RF2.20@75.535,26.785 75.535,23.285 76.07,22.75 86.43,22.75 86.93,23.25 ; RF1.19@75.535,60.695 75.535,64.285 76.25,65 86.5,65 87,64.5 RF1.1@87,60.73 ; 86.965,23.25 RF2.2@86.965,26.785
  Bottom Layer w0.254: C4.2@57.927,28.023 C4.2@57.95,28
  Bottom Layer w0.5: J5.2@47.77,37.77 49.02,37.77 49.5,37.29 ; v1(51.5,32.75) 56.927,32.75 v1(57.927,31.75) ; C4.2@57.927,28.023 v1(57.927,31.75) ; 63.125,31.125 62.05,32.2 58.95,32.2 58.5,31.75 v1(57.927,31.75) ; v1(86.945,27.75) v1(86.945,59.75)
  other v1: 70.25,4.5 75.25,4.5 80.25,4.5 70.25,9.25 75.25,9.25 80.25,9.25 85.25,9.25 70.25,14.25 75.25,14.25 80.25,14.25 85.25,14.25 70.25,19.25 75.25,19.25 80.25,19.25 85.25,19.25 70.25,24.25 80.25,24.25 85.25,24.25 70.25,29.25 64.25,31.25 80.5,34.25 85.25,34.25 35.25,38.75 85.25,39.25 80.5,39.5 80.5,44.25 85.25,44.25 35.25,45 40.75,45 45.75,45 64.338,45.044 85.25,49.25 35.25,52.5 64.25,52.5 80.5,54.25 85.25,54.25
IIN_M_2: C9B.1 C10B.1 R9B.2 U1.6 | length 35.6
  Top Layer w0.254: C9B.1@43,19.3 R9B.2@43,21.2 41.7,21.2 41.5,21 41.5,16 ; C10B.1@43.7,16 41.5,16 ; U1.6@54.025,30.225 54.025,27.775 50,23.75 50,16.75 48.75,15.5 46.242,15.5 45.937,15.195 41.805,15.195 41.5,15.5 41.5,16
IIN_M_3: C8A.2 C10A.2 R8A.2 U1.8 | length 31.6
  Top Layer w0.254: C10A.2@45.3,12.5 47.25,12.5 ; R8A.2@46,7.3 C8A.2@46,9.2 47.256,9.2 47.5,9.444 47.5,12.25 47.25,12.5 ; U1.8@55.325,30.225 55.325,26.312 53.75,24.737 53.75,15.75 50.5,12.5 47.25,12.5
IIN_P_2: C8B.2 C10B.2 R8B.2 U1.5 | length 28
  Top Layer w0.254: C10B.2@45.3,16 47.5,16 ; C8B.2@46,19.3 R8B.2@46,21.2 47.3,21.2 47.5,21 47.5,16 ; U1.5@53.375,30.225 53.375,27.875 49.5,24 49.5,16.897 48.603,16 47.5,16
IIN_P_3: C9A.1 C10A.1 R9A.2 U1.7 | length 38
  Top Layer w0.254: 41.5,12.5 C10A.1@43.7,12.5 ; R9A.2@43,7.3 C9A.1@43,9.2 41.744,9.2 41.5,9.444 41.5,13.5 41.75,13.75 45.75,13.75 46.5,13 50.25,13 53.25,16 53.25,24.975 54.675,26.4 U1.7@54.675,30.225
LED1: R2.1 U1.17 | length 16.1
  Top Layer w0.254: U1.17@57.925,35.775 v1(57.925,37.25)
  Bottom Layer w0.254: v1(57.925,37.25) 57.925,38.175 58.128,38.378 63.122,38.378 65.25,36.25 67.577,36.25 68.788,35.04 ; R2.1@68.7,34.5 R2.1@68.7,34.8 ; 68.788,35.04 68.788,34.5 68.788,35.04
LED2: J9.1 R3.1 R49.2 U1.21 | length 44.1
  Top Layer w0.254: J9.1@53,42 53,41 55.5,38.5 55.5,37 55.325,36.825 U1.21@55.325,35.775
  Bottom Layer w0.254: v1@55.325,37.5 55.325,38.647 55.514,38.836 63.311,38.836 64.647,37.5 R3.1@68.7,37.5 68.7,36.8 69.25,36.25 77.5,36.25 79.75,38.5 R49.2@79.75,47.2
  other v1: 55.5,37.5
LED3: J9.2 R4.1 R50.2 U1.22 | length 51.6
  Top Layer w0.254: J9.2@50.46,42 50.46,41.04 50.77,40.73 52.27,40.73 54.675,38.325 U1.22@54.675,35.775 v1(54.675,34)
  Bottom Layer w0.254: v1(54.675,34) 54.675,37.75 54.675,38.643 55.325,39.293 64.293,39.293 65.5,40.5 R4.1@68.7,40.5 68.7,39.8 69.25,39.25 76.75,39.25 78.25,40.75 R50.2@78.25,51.2
LED4: R5.1 R53.2 U1.25 | length 52.2
  Top Layer w0.254: v1(52.725,34) U1.25@52.725,35.775 ; v2(73.175,32.602) 74.5,33.927 74.5,39.25 73.25,40.5 v2(73.25,42)
  Bottom Layer w0.254: v1(52.725,34) 52.805,34.08 52.805,37.42 55.135,39.75 64,39.75 67.75,43.5 R5.1@68.7,43.5 70.2,42 v2(73.25,42) ; v2(73.175,32.602) 75.121,32.602 75.398,32.325 75.398,23.422 76.12,22.7 R53.2@76.75,22.7
LED5: R7.1 U1.26 | length 22.9
  Top Layer w0.254: U1.26@52.075,35.775 v1(52.075,37)
  Bottom Layer w0.254: v1(52.075,37) 52.075,37.497 54.786,40.207 63.811,40.207 67.239,43.635 67.239,45.039 R7.1@68.7,46.5
LED6: R12.1 U1.27 | length 29.9
  Top Layer w0.254: v1(51.425,34) U1.27@51.425,35.775
  Bottom Layer w0.254: v1(51.425,34) 51.25,34.175 51.25,37.318 54.596,40.664 63.621,40.664 66.703,43.747 66.703,47.503 R12.1@68.7,49.5
LED7: R17.1 RF1.3 U1.28 | length 52.1
  Top Layer w0.254: v1(50.5,38) 50.5,37 50.775,36.725 U1.28@50.775,35.775
  Bottom Layer w0.254: v1(50.5,38) 51.25,38 54.372,41.122 63.432,41.122 66.246,43.936 66.246,50.046 R17.1@68.7,52.5 68.75,52.55 68.75,55.277 73.508,60.035 74.985,60.035 75,60.02 84.965,60.02 v1(85.695,60.75)
LIVE2: LIVE_2_IN.1 LIVE_2_OUT.1 R1A.1 | length 40.8
  Top Layer w0.5: R1A.1@19.175,85 LIVE_2_OUT.1@25,85
  Bottom Layer w5.5: LIVE_2_OUT.1@25,85 LIVE_2_IN.1@60,85
LIVE_1: D8A.1 D8B.1 FR.2 LIVE_1_IN.1 NT1.2 R6A.1 R6B.1 R11A.1 R11B.1 R15A.1 R15B.1 | length 156.8
  Top Layer w0.254: R15A.1@6.5,20 7.75,20 9.05,18.7 D8A.1@9.5,18.7 10.3,19.5 R11A.1@11.95,19.5 ; R15B.1@6.75,13.1 7.6,13.1 8.8,14.3 D8B.1@9.5,14.3 ; D8B.1@9.5,14.05 10.05,13.5 R11B.1@11.95,13.5
  Top Layer w0.5: 3.5,16.5 v1(6.75,16.5) ; R15A.1@6.5,20 4.25,20 3.5,19.25 3.5,14.25 4.65,13.1 R15B.1@6.75,13.1
  Bottom Layer w0.254: LIVE_1_IN.1@59.725,13.45 59.725,14 LIVE_1_IN.1@60,14.275 61.25,14.275 NT1.2@64.246,14.275
  Bottom Layer w0.5: v1(6.75,16.5) 21,16.5 22.5,15 54,15 55,14 LIVE_1_IN.1@59.725,14 ; 17.25,31.75 46.75,31.75 52.5,26 52.5,23.25 53.25,22.5 56.75,22.5 ; 56.75,22.475 61.25,17.975 LIVE_1_IN.1@61.25,14.275
  Bottom Layer w5.5: 54,9.25 55.475,9.25 ; 54,19.25 55.25,19.25 LIVE_1_IN.1@59.725,14.725 ; 55.525,9.25 LIVE_1_IN.1@59.725,13.45
LIVE_1_A: LIVE_1_OUTA.1 R6A.2 | length 10.6
  Bottom Layer w0.254: 34.5,9.3 35.8,9.3
  Bottom Layer w5.5: LIVE_1_OUTA.1@25.234,9.3 34.5,9.3
LIVE_1B: LIVE_1_OUTB.1 R6B.2 | length 9.5
  Bottom Layer w5.5: LIVE_1_OUTB.1@25,19.3 34.5,19.3
NetC4_1: C4.1 U1.14 | length 3.2
  Top Layer w0.254: U1.14@59.225,30.225 59.975,30.225 v1(60,30.25)
  Bottom Layer w0.254: C4.1@59.55,28 59.55,29.05 60,29.5 v1(60,30.25)
NetC20_1: C20.1 U1.9 | length 2.9
  Top Layer w0.254: U1.9@55.975,30.225 55.975,29.025 56.4,28.6 C20.1@56.4,27.5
